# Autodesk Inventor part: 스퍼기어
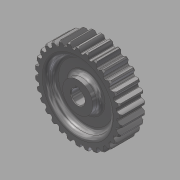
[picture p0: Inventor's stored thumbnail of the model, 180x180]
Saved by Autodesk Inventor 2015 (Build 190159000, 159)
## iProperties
Created: 2015-11
Part Number: 스퍼기어
Material: 강철, 탄소
Document SubType Name: Modeling
Designer: mduedu
Density: 1 g/cm^3
Appearance: 반광택
Author: mduedu
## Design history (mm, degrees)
sketch "스케치1"
  geometry: C1 r 28.75 at (0, 0); 1 further point
  constraints: 1 centre point, 1 coincident
  dimensions: "d0" = 57.5 diameter of C1
extrude "돌출1" new body sketch "스케치1" stored distance "d2" = 18; taper "d3" = 0 deg
sketch "스케치2" dims "d4" = 60
  geometry: L1 (0, 0)-(0, 32); L2 (-32, 0)-(32, 0); L3 (-2.07, 0)-(-2.07, 40.614); L4 (-2.07, 40.614)-(-1.57, 40.614); L5 (-1.57, 40.614)-(-1.57, 0); L6 (-0.57, 0)-(-0.57, 40.614); L7 (-0.57, 40.614)-(0, 40.614); L8 (0, 40.614)-(0, 0); A1 r 32 centre (0, 0) between (0.57, 31.995) and (-0.57, 31.995); A2 r 21.436 centre (18.143, 21.54) between (-0.57, 31.995) and (-2.07, 28.675); A3 r 21.436 centre (-18.143, 21.54) between (2.07, 28.675) and (0.57, 31.995); A4 r 32 centre (0, 0) between (32, 0) and (0.57, 31.995); A5 r 32 centre (0, 0) between (-0.57, 31.995) and (32, 0); A6 r 28.75 centre (0, 0) between (2.07, 28.675) and (-2.07, 28.675); 4 further points
  constraints: 17 point on circle, 16 end point, 6 centre point, 6 point on line, 5 perpendicular, 4 coincident, 3 symmetric about line, 2 collinear, 1 midpoint, 1 parallel, 1 vertical, 6 other
  dimensions: "d6" = 64 diameter of A1; "d7" = 0.5 distance between parallel lines of L5 L3; "d8" = 1 distance between parallel lines of L6 L5; "d9" = 40.61409 distance of L4.end L5.end; "d10" = 1.57 distance between parallel lines of L8 L5
extrude "돌출2" join sketch "스케치2" stored distance "d11" = 18; taper "d12" = 0 deg
fillet "모깎기1" dims "d16" = 0.5
chamfer "모따기3" distance "d26" = 1; stored, may be unused: second distance "d27" = 2, angle "d28" = 45 deg
sketch "스케치3"
  geometry: C1 r 23 at (0, 0); C2 r 11 at (0, 0); 1 further point
  constraints: 2 centre point, 2 coincident
  dimensions: "d32" = 46 diameter of C1; "d33" = 22 diameter of C2
extrude "돌출3" cut sketch "스케치3" distance "d34" = 6; taper "d35" = 0 deg
fillet "모깎기2" dims "d36" = 3
hole "구멍1" diameter "d39" = 10; stored, may be unused: countersink angle "d43" = 90 deg, drill point angle "d45" = 118 deg; dims "d37" = 10, "d38" = 10, "d40" = 6, "d41" = 4, "d42" = 2, "d44" = 8
sketch "스케치5"
  geometry: L1 (-1.5, 0)-(1.5, 0); L2 (1.5, 0)-(1.5, 6.4); L3 (1.5, 6.4)-(-1.5, 6.4); L4 (-1.5, 6.4)-(-1.5, 0); 2 further points
  constraints: 8 end point, 2 parallel, 1 coincident, 1 horizontal, 1 midpoint, 1 perpendicular
  dimensions: "d46" = 3 distance of L2.end L3.end; "d48" = 6.4 distance of L1.end L2.end
extrude "돌출4" cut sketch "스케치5" stored distance "d49" = 6; taper "d50" = 0 deg
chamfer "모따기4" distance "d51" = 0.5; stored, may be unused: second distance "d52" = 2, angle "d53" = 45 deg
node "솔리드1"
pattern_circular "원형 패턴3" dims "d30" = 360 deg
mirror "대칭1"
